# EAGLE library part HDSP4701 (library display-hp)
LED DISPLAY 1-character dot matrix without decimal point
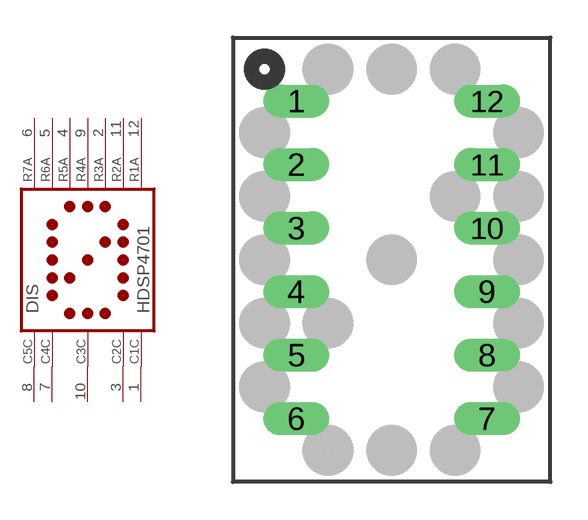
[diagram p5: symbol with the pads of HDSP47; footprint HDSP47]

Designator prefix DIS

## HDSP4701 (OC_FARNELL: unknown; OC_NEWARK: unknown)  [HDSP47]
1  C1C  pas
2  R3A  pas
3  C2C  pas
4  R5A  pas
5  R6A  pas
6  R7A  pas
7  C4C  pas
8  C5C  pas
9  R4A  pas
10  C3C  pas
11  R2A  pas
12  R1A  pas

## Footprint HDSP47 (pad centres in mm)
LED DISPLAY 17-mm 1 character dot matrix without decimal point
drill 0.813 long: 1 -3.81,6.35; 2 -3.81,3.81; 3 -3.81,1.27; 4 -3.81,-1.27; 5 -3.81,-3.81; 6 -3.81,-6.35; 7 3.81,-6.35; 8 3.81,-3.81; 9 3.81,-1.27; 10 3.81,1.27; 11 3.81,3.81; 12 3.81,6.35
